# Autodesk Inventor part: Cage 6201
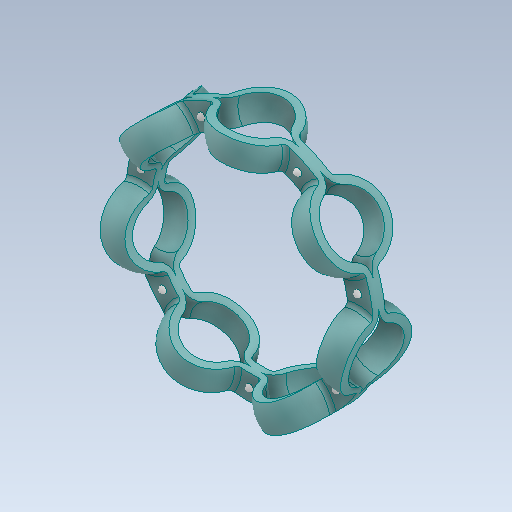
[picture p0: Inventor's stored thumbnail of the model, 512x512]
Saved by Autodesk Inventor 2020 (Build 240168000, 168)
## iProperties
Created: 2001-06
Part Number: Cage 6201
Material: Générique
Document SubType Name: Modeling
Designer: Bruno
Density: 1 g/cm^3
Appearance: Par défaut
Author: Bruno
Sending System: SolidWorks 2011
Last Author: frederic
Last Saved: 2012-02-20
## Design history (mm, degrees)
feature "Bossage-Symétrie1"
node "Solide1"
